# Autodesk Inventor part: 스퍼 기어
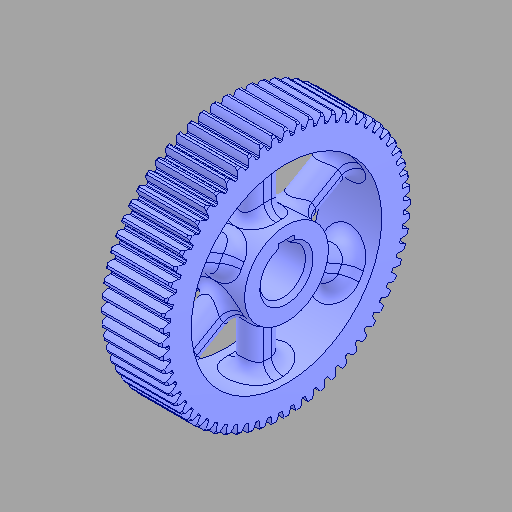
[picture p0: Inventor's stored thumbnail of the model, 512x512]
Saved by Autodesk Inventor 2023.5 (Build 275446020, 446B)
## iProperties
Created: 2026-03
Part Number: 스퍼 기어
Material: 강철, 합금
Document SubType Name: Modeling
Designer: mirae
Density: 7.73 g/cm^3
Appearance: 기본값
Author: jhkim
Sending System: Autodesk Inventor 2026
Preprocessor: ST-DEVELOPER v20.1
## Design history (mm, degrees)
node "스퍼 기어1"
node "솔리드2"
node "솔리드1"
